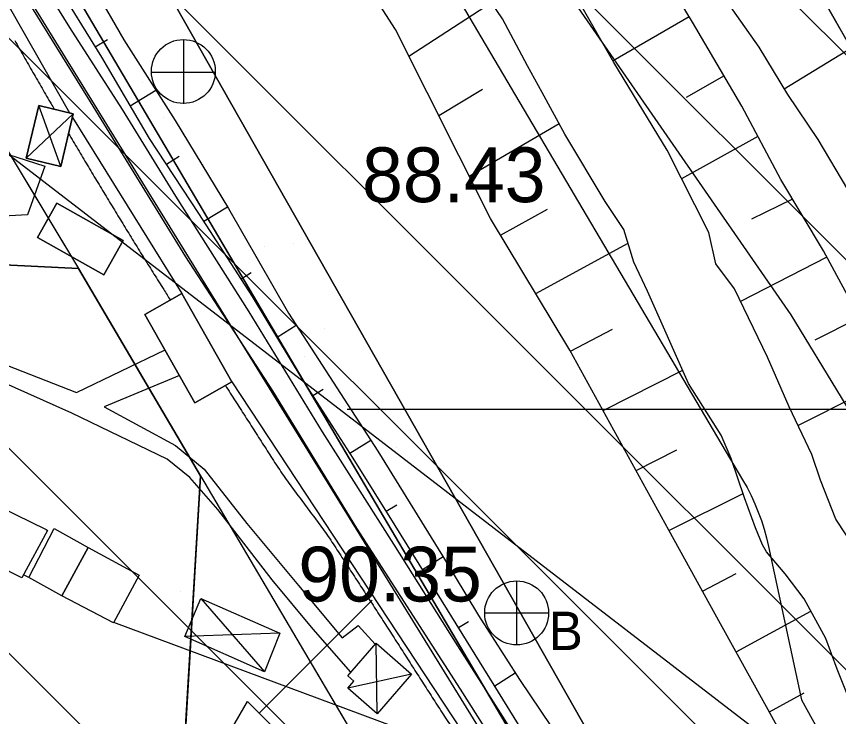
# Model space of a CAD drawing. Extents: x 417995 to 421451, y 4454518 to 4458015.
# Drawn here: x 420846.2 to 420936.2, y 4456323.2 to 4456399.9 of the extents above; entities that cross this region are included whole.
import ezdxf

# ---------------------------------------------------------------- set-up
doc = ezdxf.new("R2010")
doc.units = 0
for name, color, linetype in [('ADAKENARI', 7, 'Continuous'), ('B_Betonzemin', 7, 'Continuous'), ('B_Mesken', 7, 'Continuous'), ('B_Sundurma', 7, 'Continuous'), ('Egri_1m', 7, 'Continuous'), ('Egri_Kokurdan', 7, 'Continuous'), ('Hid_Dere_Sulu_Yat_Gen', 7, 'Continuous'), ('PL_AYA_PARK_DINLENME', 7, 'Continuous'), ('PL_SAY_SPOR', 7, 'Continuous'), ('PL_TA_K_DERE', 7, 'Continuous'), ('PL_TA_K_OTOPARK', 7, 'Continuous'), ('S_Rogar_Kapagi', 7, 'Continuous'), ('S_Rogar_Kapagi_Buski', 7, 'Continuous'), ('Sev_Sevalti', 7, 'Continuous'), ('Sev_Sevustu', 7, 'Continuous'), ('Sev_Tarama', 7, 'Continuous'), ('Sinir_Duvar_tek_tarafa_ait', 7, 'Continuous'), ('Sinir_Tel_bir_taraf', 7, 'Continuous'), ('SN_TASKIN', 7, 'Continuous'), ('SN_TR_SIVILASMA', 7, 'Continuous'), ('SN_TR_TASKIN', 7, 'Continuous'), ('TRFAT_PARKALANI', 7, 'Continuous'), ('TRFAT_SPOR', 7, 'Continuous'), ('Y_Kot_Noktasi', 7, 'Continuous'), ('Y_Yol_Kotu', 7, 'Continuous'), ('Yol_Toprak_Duz', 7, 'Continuous'), ('Yol_Toprak_Kesik', 7, 'Continuous')]:
    doc.layers.add(name, color=color, linetype=linetype)

msp = doc.modelspace()

# ---------------------------------------------------------------- linework, layer by layer
at = {"layer": 'ADAKENARI'}
for p, q in [((420781.13, 4456491.97), (420853.017, 4456372.296)), ((420983.888, 4456314.841), (420905.427, 4456453.119)), ((420924.233, 4456280.992), (420830.138, 4456440.665)), ((420852.304, 4456421.109), (420929.964, 4456284.244)), ((420748.52, 4456377.44), (420853.017, 4456372.296)), ((420866.39, 4456349.603), (420853.017, 4456372.296)), ((420866.39, 4456349.603), (420858.4, 4456215.862)), ((420866.39, 4456349.603), (420927.08, 4456246.617))]:
    msp.add_line(p, q, dxfattribs=at)
at = {"layer": 'B_Betonzemin'}
for points in [[(420812.297, 4456376.054), (420818.138, 4456373.738), (420828.811, 4456369.098), (420835.406, 4456366.199), (420844.389, 4456362.012), (420852.816, 4456358.733), (420862.502, 4456363.391)], [(420882.83, 4456328.083), (420878.733, 4456332.8), (420874.22, 4456338.195), (420868.277, 4456345.898), (420865.231, 4456349.398), (420862.744, 4456351.425), (420852.315, 4456356.464), (420844.347, 4456360.009), (420838.651, 4456362.67), (420833.602, 4456364.944), (420824.356, 4456368.851), (420811.534, 4456373.634)], [(420864.087, 4456360.593), (420855.832, 4456357.168), (420863.651, 4456352.908), (420866.794, 4456350.309), (420871.464, 4456344.38), (420877.102, 4456337.581), (420881.872, 4456331.857), (420883.637, 4456333.195), (420885.512, 4456331.17)]]:
    msp.add_lwpolyline(points, dxfattribs=at)
at = {"layer": 'B_Mesken'}
for points in [[(420838.532, 4456379.857), (420842.264, 4456385.772), (420849.351, 4456383.514), (420847.466, 4456378.176), (420842.765, 4456377.92)], [(420838.532, 4456379.857), (420842.264, 4456385.772), (420849.352, 4456383.514), (420847.465, 4456378.176), (420842.765, 4456377.92)], [(420848.556, 4456375.702), (420850.677, 4456379.461), (420857.913, 4456375.377), (420855.791, 4456371.618)], [(420848.556, 4456375.702), (420855.791, 4456371.618), (420857.913, 4456375.377), (420850.677, 4456379.46)], [(420869.804, 4456359.886), (420864.326, 4456369.556), (420860.301, 4456367.275), (420865.779, 4456357.605)], [(420869.804, 4456359.886), (420865.779, 4456357.605), (420860.301, 4456367.275), (420864.326, 4456369.556)], [(420846.829, 4456338.412), (420841.475, 4456341.109), (420844.485, 4456346.151), (420849.505, 4456343.717), (420849.645, 4456343.607)], [(420846.829, 4456338.412), (420841.475, 4456341.109), (420844.486, 4456346.151), (420849.505, 4456343.717), (420849.645, 4456343.607)], [(420851.224, 4456336.441), (420847.589, 4456338.457), (420850.386, 4456343.837), (420854.075, 4456341.745)], [(420851.224, 4456336.441), (420847.589, 4456338.457), (420850.386, 4456343.837), (420854.075, 4456341.745)], [(420854.075, 4456341.745), (420859.663, 4456338.719), (420856.856, 4456333.479), (420851.224, 4456336.441)], [(420854.075, 4456341.745), (420859.663, 4456338.719), (420856.856, 4456333.479), (420851.224, 4456336.441)]]:
    msp.add_lwpolyline(points, close=True, dxfattribs=at)
at = {"layer": 'B_Sundurma'}
for p, q in [((420851.081, 4456383.468), (420848.702, 4456390.141)), ((420852.461, 4456389.242), (420847.321, 4456384.367)), ((420866.429, 4456336.178), (420873.382, 4456328.147)), ((420875.069, 4456332.347), (420864.677, 4456332.011)), ((420885.714, 4456323.531), (420885.598, 4456331.269)), ((420889.495, 4456327.883), (420882.492, 4456326.33))]:
    msp.add_line(p, q, dxfattribs=at)
for points in [[(420851.081, 4456383.468), (420852.461, 4456389.242), (420848.702, 4456390.141), (420847.321, 4456384.367)], [(420851.081, 4456383.468), (420847.321, 4456384.367), (420848.701, 4456390.141), (420852.462, 4456389.242)], [(420866.429, 4456336.178), (420875.069, 4456332.347), (420873.382, 4456328.147), (420864.677, 4456332.011)], [(420866.429, 4456336.178), (420875.069, 4456332.347), (420873.382, 4456328.147), (420864.677, 4456332.011)], [(420889.495, 4456327.883), (420885.714, 4456323.531), (420882.492, 4456326.33), (420883.18, 4456327.123), (420882.505, 4456327.709), (420885.598, 4456331.269)], [(420889.495, 4456327.883), (420885.715, 4456323.531), (420882.492, 4456326.33), (420883.18, 4456327.123), (420882.505, 4456327.709), (420885.597, 4456331.269)]]:
    msp.add_lwpolyline(points, close=True, dxfattribs=at)
at = {"layer": 'Egri_1m'}
for points in [[(420846.063, 4456397.257), (420847.048, 4456395.516), (420848.039, 4456393.779), (420849.037, 4456392.046), (420850.041, 4456390.316), (420850.375, 4456389.741)], [(420851.943, 4456387.072), (420852.966, 4456385.354), (420853.99, 4456383.636), (420855.02, 4456381.921), (420856.054, 4456380.209), (420857.091, 4456378.499), (420858.135, 4456376.793), (420859.178, 4456375.087), (420860.229, 4456373.385), (420861.294, 4456371.692), (420862.358, 4456369.999), (420863.081, 4456368.85)], [(420869.103, 4456359.489), (420870.183, 4456357.805), (420871.263, 4456356.121), (420872.342, 4456354.438), (420873.421, 4456352.754), (420874.5, 4456351.07), (420875.616, 4456349.41), (420876.793, 4456347.793), (420877.987, 4456346.189), (420879.182, 4456344.585), (420880.35, 4456342.961), (420881.455, 4456341.294), (420882.546, 4456339.618), (420883.636, 4456337.941), (420884.725, 4456336.264), (420885.81, 4456334.583), (420886.894, 4456332.903), (420887.978, 4456331.222), (420889.053, 4456329.536), (420890.129, 4456327.849), (420891.21, 4456326.167), (420892.294, 4456324.486), (420893.38, 4456322.807), (420894.487, 4456321.141), (420895.597, 4456319.477), (420896.712, 4456317.817), (420896.883, 4456317.563)]]:
    msp.add_spline(points, degree=3, dxfattribs=at)
at = {"layer": 'Egri_Kokurdan'}
msp.add_line((420872.801, 4456323.615), (420885.175, 4456335.99), dxfattribs=at)
msp.add_lwpolyline([(420868.02, 4456318.834), (420871.52, 4456324.897), (420874.082, 4456322.334)], close=True, dxfattribs=at)
at = {"layer": 'Hid_Dere_Sulu_Yat_Gen'}
for points in [[(420938.241, 4456341.302), (420935.926, 4456344.838), (420934.252, 4456349.117), (420933.292, 4456351.938), (420930.811, 4456357.164), (420928.453, 4456362.605), (420924.82, 4456370.056), (420922.79, 4456372.793), (420922.012, 4456376.255), (420917.448, 4456385.264), (420911.637, 4456394.876), (420907.168, 4456402.686)], [(420937.908, 4456323.855), (420936.054, 4456328.439), (420934.838, 4456331.763), (420932.436, 4456336.137), (420930.385, 4456338.862), (420928.331, 4456341.283), (420927.904, 4456342.028), (420927.14, 4456343.888), (420925.936, 4456347.191), (420924.448, 4456351.487), (420923.377, 4456354.058), (420919.812, 4456359.709), (420915.307, 4456369.823), (420913.828, 4456373.009), (420912.703, 4456376.582), (420910.678, 4456379.645), (420906.261, 4456387.004), (420903.774, 4456391.575), (420902.172, 4456394.49), (420899.441, 4456399.64), (420897.651, 4456402.297)]]:
    msp.add_lwpolyline(points, dxfattribs=at)
at = {"layer": 'PL_AYA_PARK_DINLENME'}
msp.add_lwpolyline([(420398.451, 4456770.435), (420341.542, 4456780.97), (420343.747, 4456814.103), (420500.975, 4456742.521), (420572.513, 4456705.355), (420639.693, 4456661.01), (420701.864, 4456609.89), (420758.351, 4456552.552), (420808.535, 4456489.624), (420852.304, 4456421.109), (420929.964, 4456284.244), (420924.233, 4456280.992), (420830.138, 4456440.665), (420780.571, 4456521.605), (420657.58, 4456639.752), (420530.801, 4456712.428), (420483.239, 4456735.932), (420462.904, 4456746.949), (420444.362, 4456753.772)], close=True, dxfattribs=at)
for points in [[(420806.621, 4456538.493), (420839.115, 4456497.136), (420881.948, 4456423.286), (420925.715, 4456349.165), (420926.198, 4456348.307), (420926.647, 4456347.431), (420927.06, 4456346.537), (420927.436, 4456345.627), (420927.776, 4456344.702), (420928.078, 4456343.765), (420928.342, 4456342.816), (420928.568, 4456341.858), (420932.166, 4456325.065), (420943.982, 4456303.649), (421053.63, 4456151.536)], [(420948.801, 4456322.543), (420948.505, 4456324.889), (420948.406, 4456327.252), (420948.406, 4456328.741), (420947.446, 4456334.501), (420947.078, 4456336.425), (420946.62, 4456338.33), (420946.071, 4456340.21), (420945.434, 4456342.063), (420944.71, 4456343.883), (420943.9, 4456345.666), (420943.006, 4456347.41), (420942.031, 4456349.108), (420931.049, 4456367.229), (420903.88, 4456406.473), (420864.637, 4456469.111), (420850.298, 4456502.316), (420823.885, 4456533.258)], [(421036.852, 4456094.936), (420796.811, 4456484.246), (420794.892, 4456487.096), (420792.752, 4456489.784), (420790.403, 4456492.291), (420787.862, 4456494.603), (420785.143, 4456496.704), (420782.266, 4456498.581), (420779.247, 4456500.221), (420776.107, 4456501.615), (420767.72, 4456504.943), (420764.74, 4456506.197), (420761.814, 4456507.572), (420758.947, 4456509.066), (420756.143, 4456510.675), (420753.408, 4456512.399), (420750.746, 4456514.233), (420748.161, 4456516.174), (420745.657, 4456518.22)]]:
    msp.add_lwpolyline(points, dxfattribs=at)
at = {"layer": 'PL_SAY_SPOR'}
msp.add_lwpolyline([(420858.4, 4456215.862), (420846.759, 4456021.023), (420843.586, 4456018.223), (420716.312, 4456026.515), (420714.2, 4456029.578), (420727.853, 4456073.983), (420731.55, 4456128.29), (420748.52, 4456377.44), (420853.017, 4456372.296), (420866.39, 4456349.603)], close=True, dxfattribs=at)
at = {"layer": 'PL_TA_K_DERE'}
msp.add_lwpolyline([(420859.034, 4456525.74), (420905.427, 4456453.119), (420983.888, 4456314.841), (420929.964, 4456284.244), (420852.304, 4456421.109), (420808.535, 4456489.624), (420758.351, 4456552.552), (420701.864, 4456609.89), (420639.693, 4456661.01), (420572.513, 4456705.355), (420500.975, 4456742.521), (420343.747, 4456814.103), (420348.148, 4456880.222), (420452.948, 4456832.51), (420528.13, 4456798.281), (420603.968, 4456758.881), (420676.56, 4456710.964), (420743.751, 4456655.717), (420804.798, 4456593.749)], close=True, dxfattribs=at)
for points in [[(420806.621, 4456538.493), (420839.115, 4456497.136), (420881.948, 4456423.286), (420925.715, 4456349.165), (420926.198, 4456348.307), (420926.647, 4456347.431), (420927.06, 4456346.537), (420927.436, 4456345.627), (420927.776, 4456344.702), (420928.078, 4456343.765), (420928.342, 4456342.816), (420928.568, 4456341.858), (420932.166, 4456325.065), (420943.982, 4456303.649), (421053.63, 4456151.536)], [(420948.801, 4456322.543), (420948.505, 4456324.889), (420948.406, 4456327.252), (420948.406, 4456328.741), (420947.446, 4456334.501), (420947.078, 4456336.425), (420946.62, 4456338.33), (420946.071, 4456340.21), (420945.434, 4456342.063), (420944.71, 4456343.883), (420943.9, 4456345.666), (420943.006, 4456347.41), (420942.031, 4456349.108), (420931.049, 4456367.229), (420903.88, 4456406.473), (420864.637, 4456469.111), (420850.298, 4456502.316), (420823.885, 4456533.258)]]:
    msp.add_lwpolyline(points, dxfattribs=at)
at = {"layer": 'PL_TA_K_OTOPARK'}
for points in [[(420748.52, 4456377.44), (420756.36, 4456492.63), (420781.13, 4456491.97), (420853.017, 4456372.296)], [(420866.39, 4456349.603), (420927.08, 4456246.617), (420873.373, 4456214.968), (420858.4, 4456215.862)]]:
    msp.add_lwpolyline(points, close=True, dxfattribs=at)
at = {"layer": 'S_Rogar_Kapagi'}
for p, q in [((420864.56, 4456390.346), (420864.56, 4456397.346)), ((420860.99, 4456393.811), (420867.99, 4456393.811))]:
    msp.add_line(p, q, dxfattribs=at)
msp.add_circle((420864.507, 4456393.874), 3.5, dxfattribs=at)
at = {"layer": 'S_Rogar_Kapagi_Buski'}
for p, q in [((420900.987, 4456338.081), (420900.987, 4456331.081)), ((420897.487, 4456334.581), (420904.487, 4456334.581))]:
    msp.add_line(p, q, dxfattribs=at)
msp.add_circle((420900.987, 4456334.581), 3.5, dxfattribs=at)
at = {"layer": 'Sev_Sevalti'}
for points in [[(420896.925, 4456448.614), (420898.442, 4456445.151), (420900.43, 4456441.05), (420902.323, 4456437.223), (420903.446, 4456434.492), (420905.613, 4456429.922), (420908.465, 4456425.235), (420910.739, 4456421.337), (420914.285, 4456416.446), (420916.805, 4456412.263), (420920.55, 4456406.651), (420923.493, 4456402.278), (420927.497, 4456396.522), (420930.626, 4456391.353), (420933.954, 4456386.432), (420937.2, 4456380.946)], [(420839.429, 4456425.887), (420847.445, 4456414.254), (420853.788, 4456404.649), (420858.007, 4456397.326), (420863.609, 4456388.49), (420869.442, 4456378.879), (420876.014, 4456367.393), (420885.804, 4456352.299), (420892.877, 4456340.85), (420896.811, 4456334.291), (420901.283, 4456327.28), (420908.216, 4456316.985)], [(420938.241, 4456341.302), (420935.926, 4456344.838), (420934.252, 4456349.117), (420933.292, 4456351.938), (420930.811, 4456357.164), (420928.453, 4456362.605), (420924.82, 4456370.056), (420922.79, 4456372.793), (420922.012, 4456376.255), (420917.448, 4456385.264), (420911.637, 4456394.876), (420907.168, 4456402.686)], [(420937.908, 4456323.855), (420936.054, 4456328.439), (420934.838, 4456331.763), (420932.436, 4456336.137), (420930.385, 4456338.862), (420928.331, 4456341.283), (420927.904, 4456342.028), (420927.14, 4456343.888), (420925.936, 4456347.191), (420924.448, 4456351.487), (420923.377, 4456354.058), (420919.812, 4456359.709), (420915.307, 4456369.823), (420913.828, 4456373.009), (420912.703, 4456376.582), (420910.678, 4456379.645), (420906.261, 4456387.004), (420903.774, 4456391.575), (420902.172, 4456394.49), (420899.441, 4456399.64), (420897.651, 4456402.297)]]:
    msp.add_lwpolyline(points, dxfattribs=at)
at = {"layer": 'Sev_Sevustu'}
for points in [[(420932.28, 4456317.144), (420928.342, 4456324.311), (420923.296, 4456333.401), (420917.634, 4456343.648), (420906.822, 4456363.356), (420898.122, 4456377.785), (420887.733, 4456398.466), (420883.635, 4456404.852), (420877.795, 4456414.82), (420868.364, 4456431.776), (420859.08, 4456448.34), (420849.176, 4456465.779), (420839.365, 4456483.76), (420832.143, 4456496.327), (420840.133, 4456501.062)], [(420963.516, 4456317.477), (420960.105, 4456324.659), (420955.581, 4456333.465), (420951.346, 4456341.864), (420946.022, 4456353.135), (420941.333, 4456361.747), (420934.565, 4456374.221), (420929.899, 4456382.028), (420925.627, 4456390.059), (420920.237, 4456399.288), (420915.484, 4456407.129), (420911.017, 4456414.282), (420905.796, 4456422.14), (420901.447, 4456429.182), (420898.512, 4456434.164), (420896.224, 4456437.735), (420893.827, 4456441.309), (420891.785, 4456445.464), (420889.595, 4456449.078)], [(420904.629, 4456316.819), (420899.007, 4456325.916), (420893.406, 4456334.916), (420887.7, 4456344.166), (420883.079, 4456351.526), (420877.508, 4456360.232), (420872.07, 4456369.229), (420866.209, 4456378.34), (420860.817, 4456386.534), (420855.573, 4456395.432), (420852.171, 4456400.975), (420846.876, 4456409.189), (420841.464, 4456417.611)]]:
    msp.add_lwpolyline(points, dxfattribs=at)
at = {"layer": 'Sev_Tarama'}
for p, q in [((420889.193, 4456395.56), (420898.243, 4456401.419)), ((420919.881, 4456399.874), (420911.535, 4456395.054)), ((420854.874, 4456396.571), (420856.189, 4456397.385)), ((420939.836, 4456397.798), (420930.272, 4456391.938)), ((420923.684, 4456393.386), (420919.545, 4456391.013)), ((420858.704, 4456390.118), (420861.481, 4456391.847)), ((420892.466, 4456389.043), (420897.237, 4456391.921)), ((420895.792, 4456382.422), (420905.628, 4456388.168)), ((420927.392, 4456386.741), (420919.032, 4456382.136)), ((420862.655, 4456383.74), (420864.046, 4456384.61)), ((420866.767, 4456377.473), (420869.334, 4456379.058)), ((420931.178, 4456379.888), (420926.679, 4456377.696)), ((420899.218, 4456375.966), (420904.354, 4456378.795)), ((420903.08, 4456369.561), (420913.177, 4456375.076)), ((420934.925, 4456373.557), (420925.485, 4456368.691)), ((420870.825, 4456371.164), (420871.945, 4456371.857)), ((420938.523, 4456366.926), (420933.63, 4456364.439)), ((420874.762, 4456364.774), (420876.859, 4456366.091)), ((420906.887, 4456363.237), (420911.49, 4456365.648)), ((420910.456, 4456356.732), (420919.165, 4456361.162)), ((420942.12, 4456360.302), (420931.787, 4456355.109)), ((420878.69, 4456358.384), (420879.815, 4456359.092)), ((420882.732, 4456352.068), (420885.023, 4456353.504)), ((420914.049, 4456350.182), (420918.519, 4456352.428)), ((420917.652, 4456343.616), (420925.77, 4456347.669)), ((420886.722, 4456345.723), (420887.859, 4456346.427)), ((420890.671, 4456339.349), (420892.938, 4456340.748)), ((420921.326, 4456336.967), (420925.028, 4456338.89)), ((420925.01, 4456330.313), (420933.193, 4456334.758)), ((420894.618, 4456332.968), (420895.706, 4456333.644)), ((420898.585, 4456326.594), (420900.818, 4456328.009)), ((420928.646, 4456323.758), (420932.46, 4456325.826))]:
    msp.add_line(p, q, dxfattribs=at)
at = {"layer": 'Sinir_Duvar_tek_tarafa_ait'}
msp.add_lwpolyline([(420847.589, 4456338.457), (420847.019, 4456338.763)], dxfattribs=at)
at = {"layer": 'Sinir_Tel_bir_taraf'}
for points in [[(420788.924, 4456490.92), (420791.617, 4456487.454), (420798.68, 4456477.968), (420803.505, 4456472.288), (420806.949, 4456463.69), (420810.279, 4456458.353), (420817.982, 4456445.928), (420825.536, 4456433.7), (420831.629, 4456422.943), (420839.112, 4456412.107), (420852.049, 4456389.34)], [(420852.367, 4456388.845), (420864.326, 4456369.556)], [(420869.804, 4456359.886), (420897.011, 4456318.583), (420856.887, 4456333.537)]]:
    msp.add_lwpolyline(points, dxfattribs=at)
at = {"layer": 'SN_TASKIN'}
msp.add_lwpolyline([(421279.092, 4456215.61), (421195.311, 4456240.09), (421032.227, 4456272.975), (420928.588, 4456320.689), (420834.213, 4456393.35), (420746.644, 4456480.517), (420663.922, 4456586.466), (420574.108, 4456669.499), (420422.961, 4456744.082), (420282.113, 4456812.001), (420160.798, 4456835.053), (420091.41, 4456837.401), (419960.894, 4456961.809), (419854.401, 4457049.617), (419750.612, 4457217.328), (419705.667, 4457319.894), (419669.268, 4457550.581), (419656.393, 4457729.951), (419636.417, 4457793.064)], dxfattribs=at)
at = {"layer": 'SN_TR_SIVILASMA'}
for p, q in [((421277.42, 4456055.312), (419975.727, 4457357.006)), ((421277.189, 4456033.093), (419969.646, 4457340.635)), ((421276.725, 4455988.655), (419957.486, 4457307.895)), ((421276.493, 4455966.436), (419971.974, 4457270.956)), ((421276.03, 4455921.999), (420004.046, 4457193.982)), ((421275.798, 4455899.78), (420015.354, 4457160.224))]:
    msp.add_line(p, q, dxfattribs=at)
at = {"layer": 'SN_TR_TASKIN'}
msp.add_line((420882.431, 4456356.904), (420982.431, 4456356.904), dxfattribs=at)
at = {"layer": 'TRFAT_PARKALANI'}
for p, q in [((420865.278, 4456397.301), (420865.278, 4456397.301)), ((420860.017, 4456392.722), (420860.017, 4456392.722)), ((420862.354, 4456388.861), (420862.354, 4456388.861)), ((420866.678, 4456383.742), (420866.678, 4456383.742)), ((420873.338, 4456374.762), (420873.338, 4456374.762)), ((420876.578, 4456375.001), (420876.578, 4456375.001)), ((420879.999, 4456365.782), (420879.999, 4456365.782)), ((420877.808, 4456362.666), (420877.808, 4456362.666)), ((420886.659, 4456356.802), (420886.659, 4456356.802)), ((420887.877, 4456352.7), (420887.877, 4456352.7)), ((420893.32, 4456347.822), (420893.32, 4456347.822)), ((420893.261, 4456336.47), (420893.261, 4456336.47)), ((420899.176, 4456330.399), (420899.176, 4456330.399))]:
    msp.add_line(p, q, dxfattribs=at)
at = {"layer": 'TRFAT_SPOR'}
msp.add_line((420864.2, 4456336.973), (420864.2, 4456336.973), dxfattribs=at)
at = {"layer": 'Yol_Toprak_Duz'}
msp.add_lwpolyline([(420789.26, 4456492.92), (420795.421, 4456485.04), (420803.339, 4456475.168), (420810.328, 4456461.944), (420821.051, 4456443.06), (420829.121, 4456429.476), (420833.084, 4456423.054), (420843.525, 4456407.947), (420854.01, 4456391.04), (420864.727, 4456373.565), (420874.282, 4456358.902), (420883.443, 4456343.853), (420894.787, 4456326.22), (420905.746, 4456308.981), (420915.468, 4456293.731), (420926.08, 4456276.518), (420938.844, 4456255.853), (420947.832, 4456240.871), (420958.275, 4456224.138), (420967.604, 4456210.497), (420975.273, 4456197.937)], dxfattribs=at)
at = {"layer": 'Yol_Toprak_Kesik'}
msp.add_lwpolyline([(420905.81, 4456313.198), (420899.468, 4456323.245), (420894.31, 4456331.388), (420887.562, 4456342.124), (420879.744, 4456354.394), (420871.698, 4456367.568), (420863.678, 4456380.209), (420857.84, 4456389.718), (420852.083, 4456398.705), (420846.554, 4456407.656), (420842.747, 4456413.165), (420838.61, 4456419.341), (420833.391, 4456427.799), (420825.019, 4456441.032), (420817.25, 4456454.701), (420811.363, 4456464.699), (420807.515, 4456472.294), (420804.979, 4456476.842), (420804.002, 4456478.885), (420804.085, 4456479.405), (420804.251, 4456479.685), (420805.237, 4456480.535)], dxfattribs=at)

# ---------------------------------------------------------------- texts
at = {"layer": 'S_Rogar_Kapagi_Buski'}
msp.add_text('B', height=4.2, dxfattribs=at).set_placement((420904.487, 4456330.516))
at = {"layer": 'Y_Kot_Noktasi'}
msp.add_text('88.43', height=6, dxfattribs=at).set_placement((420884.068, 4456379.563))
at = {"layer": 'Y_Yol_Kotu'}
msp.add_text('90.35', height=6, dxfattribs=at).set_placement((420877.093, 4456335.833))

doc.saveas('drawing.dxf')
